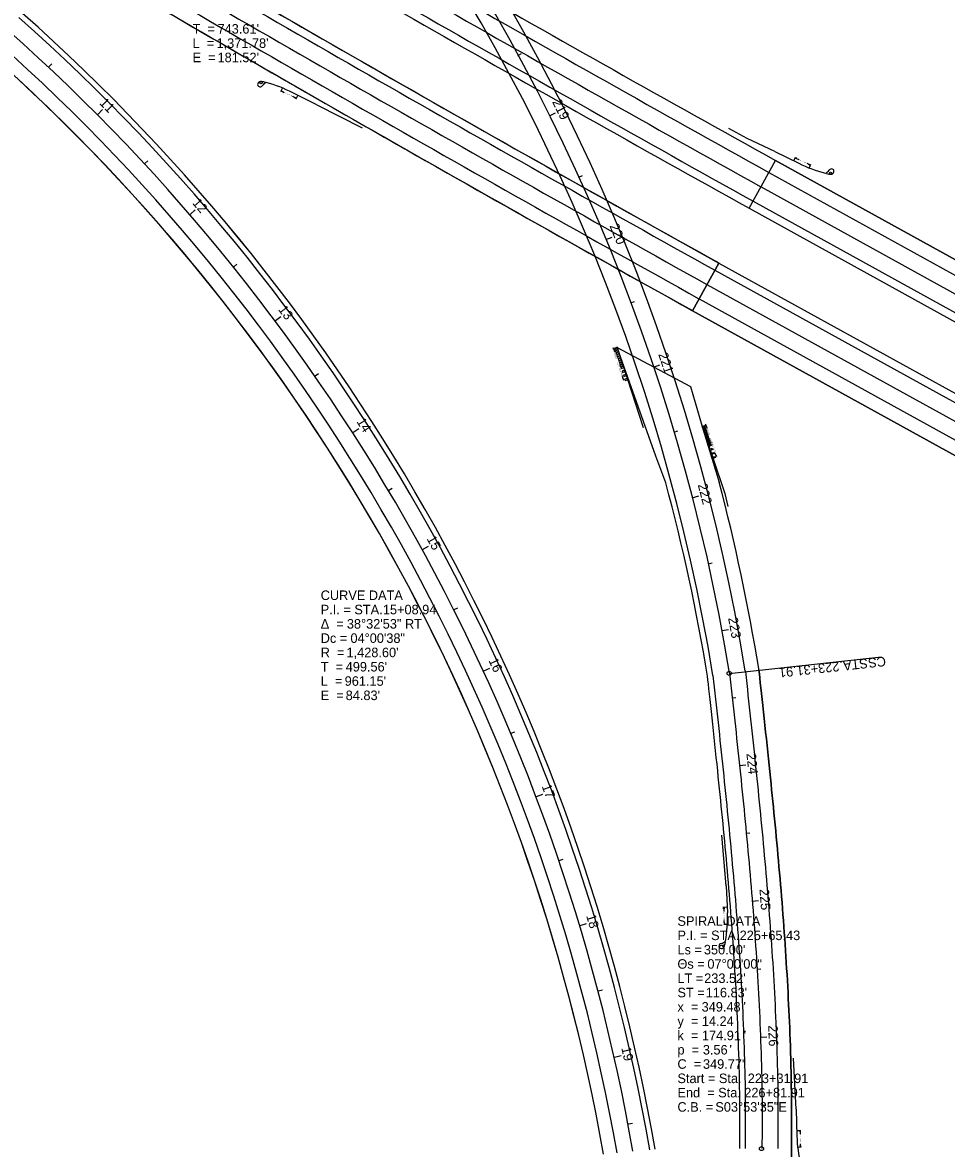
# Model space of a CAD drawing. Extents: x 76539 to 88870, y 518807 to 527554.
# Drawn here: x 87208 to 87887, y 521842 to 522669 of the extents above; entities that cross this region are included whole.
import ezdxf

# ---------------------------------------------------------------- set-up
doc = ezdxf.new("R2010")
doc.units = 0
for name, color, linetype in [('Default', 7, 'Continuous'), ('GE_P_Alignment_100_Cardinal_Points', 7, 'Continuous'), ('GE_P_Alignment_100_Curve_Data', 7, 'Continuous'), ('GE_P_Alignment_100_Stations', 7, 'Continuous'), ('PM_P_Edge_Line', 7, 'Continuous'), ('PM_P_Lane_Line', 7, 'Continuous'), ('PV_P_Shoulder', 7, 'Continuous'), ('RD_P_GR_Lt', 7, 'Continuous'), ('RD_P_GR_Rt', 7, 'Continuous'), ('SC_Scratch1', 7, 'Continuous'), ('SC_Scratch13', 7, 'Continuous'), ('XS_P_Pavt_Surface', 7, 'Continuous')]:
    doc.layers.add(name, color=color, linetype=linetype)

msp = doc.modelspace()

# ---------------------------------------------------------------- linework, layer by layer
at = {"layer": 'Default'}
for points in [[(87727.6, 522191.42), (87728.86, 522179.82), (87731.39, 522156.63), (87735.11, 522121.82), (87738.65, 522087), (87741.93, 522052.15), (87744.88, 522017.27), (87747.39, 521982.36), (87749.41, 521947.41), (87750.8, 521912.43), (87751.57, 521877.43), (87751.42, 521854.09), (87751.35, 521842.42)], [(87739.2, 522192.69), (87740.46, 522181.08), (87743, 522157.87), (87746.71, 522123.02), (87750.26, 522088.13), (87753.55, 522053.18), (87756.51, 522018.17), (87759.04, 521983.1), (87761.06, 521947.97), (87762.46, 521912.77), (87763.24, 521877.6), (87763.09, 521854.17), (87763.01, 521842.48)], [(87773.02, 521842.55), (87773.03, 521849.2), (87773.33, 521872.31), (87772.44, 521914.51), (87771.06, 521947.92), (87769.03, 521983.64), (87766.5, 522018.71), (87763.55, 522053.72), (87760.19, 522089.26), (87756.83, 522122.44), (87752.37, 522164.24), (87749.86, 522187.15), (87749.14, 522193.77)]]:
    msp.add_open_spline(points, degree=3, dxfattribs=at)
at = {"layer": 'GE_P_Alignment_100_Cardinal_Points'}
msp.add_line((87727.27, 522191.38), (87839.1, 522203.58), dxfattribs=at)
for centre in [(87727.27, 522191.38), (87751.01, 521842.42)]:
    msp.add_circle(centre, 1.5, dxfattribs=at)
at = {"layer": 'GE_P_Alignment_100_Stations'}
for p, q in [((87572.1, 522645.23), (87574.73, 522646.66)), ((87227.56, 522636.73), (87229.62, 522638.92)), ((87263.4, 522601.87), (87266.95, 522605.39)), ((87595.19, 522600.89), (87599.67, 522603.12)), ((87297.99, 522565.77), (87300.2, 522567.81)), ((87616.73, 522555.77), (87619.46, 522557.01)), ((87331.3, 522528.49), (87335.09, 522531.75)), ((87636.68, 522509.92), (87641.3, 522511.83)), ((87363.29, 522490.06), (87365.63, 522491.94)), ((87655.01, 522463.41), (87657.82, 522464.46)), ((87393.91, 522450.54), (87397.92, 522453.53)), ((87671.71, 522416.28), (87676.45, 522417.87)), ((87423.13, 522409.97), (87425.6, 522411.68)), ((87450.91, 522368.4), (87455.12, 522371.11)), ((87686.76, 522368.6), (87689.64, 522369.45)), ((87477.22, 522325.89), (87479.8, 522327.42)), ((87700.13, 522320.42), (87704.97, 522321.68)), ((87502.03, 522282.48), (87506.41, 522284.88)), ((87711.82, 522271.81), (87714.74, 522272.46)), ((87525.3, 522238.23), (87527.98, 522239.58)), ((87721.79, 522222.82), (87726.71, 522223.73)), ((87547.01, 522193.19), (87551.56, 522195.28)), ((87729.23, 522173.4), (87732.21, 522173.72)), ((87567.13, 522147.42), (87569.9, 522148.58)), ((87734.55, 522123.68), (87739.52, 522124.2)), ((87585.64, 522100.97), (87590.32, 522102.74)), ((87739.53, 522073.93), (87742.52, 522074.22)), ((87602.51, 522053.91), (87605.35, 522054.87)), ((87743.93, 522024.13), (87748.91, 522024.53)), ((87617.72, 522006.28), (87622.51, 522007.72)), ((87747.49, 521974.25), (87750.48, 521974.44)), ((87631.26, 521958.15), (87634.16, 521958.91)), ((87749.96, 521924.32), (87754.96, 521924.5)), ((87643.11, 521909.58), (87647.98, 521910.67)), ((87751.1, 521874.33), (87754.1, 521874.36)), ((87653.24, 521860.62), (87656.19, 521861.17))]:
    msp.add_line(p, q, dxfattribs=at)
at = {"layer": 'PM_P_Edge_Line'}
for p, q in [((87756.48, 522559.22), (87756.49, 522559.21)), ((87756.49, 522559.21), (88837.59, 521962.47)), ((87744.82, 522538.24), (87744.86, 522538.22)), ((87744.86, 522538.22), (88825.99, 521941.45)), ((87716.74, 522487.52), (87716.78, 522487.5)), ((87716.78, 522487.5), (88840.17, 521867.4)), ((87705.09, 522466.54), (87705.15, 522466.5)), ((87705.15, 522466.5), (88828.57, 521846.39)), ((87739.11, 522193.31), (87739.16, 522193)), ((87739.11, 522193.31), (87739.16, 522193)), ((87739.16, 522193), (87739.2, 522192.69)), ((87739.16, 522193), (87739.2, 522192.69)), ((87739.02, 521842.59), (87739.01, 521842.36))]:
    msp.add_line(p, q, dxfattribs=at)
for centre, radius, start, end in [((86313.45, 521961.45), 1444.39, 9.23728, 64.10866), ((86313.45, 521961.45), 1444.39, 9.23728, 64.10866), ((86313.45, 521961.45), 1420.39, 9.24998, 64.10866), ((98861.51, 542544.07), 22862.98, 239.568441, 240.940285), ((98861.51, 542544.07), 22886.98, 239.568441, 240.940285), ((98861.51, 542544.07), 22944.95, 239.568441, 240.940516), ((98861.51, 542544.07), 22968.95, 239.568441, 240.940516), ((86249.47, 521595.47), 1440.6, 9.83522, 48.42092), ((86249.47, 521595.47), 1416.6, 9.91089, 48.42092)]:
    msp.add_arc(centre, radius, start, end, dxfattribs=at)
for points in [[(87739.2, 522192.69), (87740.46, 522181.08), (87743, 522157.87), (87746.71, 522123.02), (87750.26, 522088.13), (87753.55, 522053.18), (87756.51, 522018.17), (87759.04, 521983.1), (87761.06, 521947.97), (87762.46, 521912.77), (87763.24, 521877.6), (87763.09, 521854.17), (87763.01, 521842.48)], [(87715.37, 522189.77), (87716.63, 522178.28), (87719.14, 522155.21), (87722.84, 522120.55), (87726.37, 522085.81), (87729.65, 522051.06), (87732.58, 522016.32), (87735.09, 521981.57), (87737.09, 521946.82), (87738.47, 521912.06), (87739.24, 521877.32), (87739.09, 521854.16), (87739.02, 521842.59)]]:
    msp.add_open_spline(points, degree=3, dxfattribs=at)
at = {"layer": 'PM_P_Lane_Line'}
for p, q in [((87750.65, 522548.73), (87750.68, 522548.72)), ((87750.68, 522548.72), (88831.79, 521951.96)), ((87710.91, 522477.03), (87710.96, 522477)), ((87710.96, 522477), (88834.37, 521856.9)), ((87727.6, 522191.44), (87727.6, 522191.43)), ((87727.6, 522191.43), (87727.6, 522191.42))]:
    msp.add_line(p, q, dxfattribs=at)
for centre, radius, start, end in [((86313.45, 521961.45), 1432.72, 9.23728, 64.10866), ((98861.51, 542544.07), 22874.98, 239.568441, 240.940285), ((98861.51, 542544.07), 22956.95, 239.568441, 240.940516), ((86249.47, 521595.47), 1428.27, 9.87385, 48.42092)]:
    msp.add_arc(centre, radius, start, end, dxfattribs=at)
at = {"layer": 'PV_P_Shoulder'}
for p, q in [((87761.34, 522567.96), (88842.42, 521971.22)), ((87741.91, 522533), (87741.96, 522532.97)), ((87741.96, 522532.97), (88820.79, 521937.47)), ((87719.66, 522492.76), (87719.68, 522492.75)), ((87719.68, 522492.75), (88843.07, 521872.66)), ((87700.23, 522457.8), (87700.3, 522457.76)), ((87700.3, 522457.76), (88823.74, 521837.64)), ((87673.43, 522350.94), (87645.03, 522430.75)), ((87707.42, 522372.8), (87719.87, 522331.9)), ((87680.69, 522331.33), (87673.43, 522350.94)), ((87749.08, 522194.34), (87748.98, 522194.92)), ((87749.14, 522193.77), (87749.08, 522194.34)), ((87735.01, 521842.35), (87735.02, 521842.61)), ((87781.67, 521223.03), (87773.02, 521842.55))]:
    msp.add_line(p, q, dxfattribs=at)
for centre, radius, start, end in [((98861.51, 542544.07), 22852.98, 239.568441, 240.940285), ((98861.51, 542544.07), 22892.98, 239.568441, 240.940285), ((98861.51, 542544.07), 22938.95, 239.568441, 240.940516), ((98861.51, 542544.07), 22978.95, 239.568441, 240.940516), ((86249.47, 521595.47), 1444.6, 9.8228, 48.42092), ((86249.47, 521595.47), 1406.6, 9.94301, 48.42092), ((86313.45, 521961.45), 1454.39, 9.23728, 14.75662), ((86313.45, 521961.45), 1416.39, 9.25428, 15.13785)]:
    msp.add_arc(centre, radius, start, end, dxfattribs=at)
msp.add_open_spline([(87735.02, 521842.61), (87735.03, 521849.22), (87735.33, 521872.02), (87734.45, 521913.53), (87733.09, 521946.44), (87731.08, 521981.62), (87728.58, 522016.2), (87725.66, 522050.76), (87722.34, 522085.87), (87719.02, 522118.68), (87714.61, 522159.99), (87712.12, 522182.65), (87711.41, 522189.23)], degree=3, dxfattribs=at)
at = {"layer": 'RD_P_GR_Lt'}
for p, q in [((87424.3, 522608.9), (87406.68, 522617.81)), ((87760.71, 522574.74), (87778.4, 522565.98)), ((87644.84, 522431.33), (87652.52, 522407.54)), ((87707.22, 522373.37), (87715.21, 522349.68)), ((87725.17, 522035.31), (87721.93, 522072.67)), ((87776.45, 521871.32), (87777.01, 521851.58))]:
    msp.add_line(p, q, dxfattribs=at)
for points in [[(87643.38, 522429.73), (87643.68, 522428.79), (87645.47, 522429.37), (87645.17, 522430.31)], [(87643.86, 522428.25), (87644.16, 522427.31), (87645.95, 522427.89), (87645.65, 522428.82)], [(87644.34, 522426.76), (87644.64, 522425.82), (87646.43, 522426.4), (87646.13, 522427.34)], [(87644.82, 522425.27), (87645.12, 522424.33), (87646.91, 522424.91), (87646.61, 522425.85)], [(87645.3, 522423.79), (87645.6, 522422.85), (87647.39, 522423.42), (87647.09, 522424.36)], [(87645.78, 522422.3), (87646.08, 522421.36), (87647.87, 522421.94), (87647.57, 522422.88)], [(87646.25, 522420.81), (87646.56, 522419.87), (87648.35, 522420.45), (87648.05, 522421.39)], [(87646.73, 522419.32), (87647.04, 522418.39), (87648.83, 522418.96), (87648.53, 522419.9)], [(87647.21, 522417.84), (87647.52, 522416.9), (87649.31, 522417.48), (87649.01, 522418.42)], [(87647.69, 522416.35), (87648, 522415.41), (87649.79, 522415.99), (87649.49, 522416.93)], [(87648.65, 522413.38), (87648.96, 522412.44), (87650.75, 522413.02), (87650.45, 522413.95)], [(87649.61, 522410.4), (87649.92, 522409.46), (87651.71, 522410.04), (87651.41, 522410.98)], [(87650.57, 522407.43), (87650.87, 522406.49), (87652.67, 522407.07), (87652.37, 522408.01)], [(87709.35, 522372.96), (87709.67, 522372.03), (87707.88, 522371.43), (87707.56, 522372.36)], [(87709.85, 522371.48), (87710.16, 522370.55), (87708.38, 522369.94), (87708.06, 522370.88)], [(87710.35, 522370), (87710.66, 522369.07), (87708.88, 522368.46), (87708.56, 522369.4)], [(87710.85, 522368.52), (87711.16, 522367.59), (87709.38, 522366.98), (87709.06, 522367.92)], [(87711.35, 522367.04), (87711.66, 522366.11), (87709.88, 522365.5), (87709.56, 522366.44)], [(87711.85, 522365.56), (87712.16, 522364.62), (87710.38, 522364.02), (87710.06, 522364.96)], [(87712.35, 522364.08), (87712.66, 522363.14), (87710.88, 522362.54), (87710.56, 522363.48)], [(87712.85, 522362.6), (87713.16, 522361.66), (87711.38, 522361.06), (87711.06, 522362)], [(87713.34, 522361.12), (87713.66, 522360.18), (87711.87, 522359.58), (87711.56, 522360.52)], [(87713.84, 522359.64), (87714.16, 522358.7), (87712.37, 522358.1), (87712.06, 522359.04)], [(87714.84, 522356.68), (87715.16, 522355.74), (87713.37, 522355.14), (87713.06, 522356.07)], [(87715.84, 522353.71), (87716.16, 522352.78), (87714.37, 522352.18), (87714.06, 522353.11)], [(87716.84, 522350.75), (87717.15, 522349.82), (87715.37, 522349.22), (87715.05, 522350.15)]]:
    msp.add_lwpolyline(points, close=True, dxfattribs=at)
msp.add_lwpolyline([(87715.21, 522349.68), (87724.02, 522323.56), (87726.35, 522313.88)], dxfattribs=at)
for centre, start, end in [((87361.32, 522528.12), 63.17242, 75.07742), ((87823.02, 522656.03), 243.63945, 255.54445), ((87877.48, 521854.44), 181.62988, 193.53487)]:
    msp.add_arc(centre, 100.51, start, end, dxfattribs=at)
at = {"layer": 'RD_P_GR_Rt'}
for p, q in [((87424.3, 522608.9), (87457.76, 522591.98)), ((87652.52, 522407.54), (87664.03, 522371.84)), ((87725.17, 522035.31), (87725.97, 522015.59)), ((87776.45, 521871.32), (87774.44, 521908.89))]:
    msp.add_line(p, q, dxfattribs=at)
msp.add_lwpolyline([(87760.71, 522574.74), (87740.49, 522584.11), (87727.11, 522591.59)], dxfattribs=at)
for centre in [(87383.33, 522625.25), (87801.81, 522558.73), (87723.06, 521991.26)]:
    msp.add_circle(centre, 0.79, dxfattribs=at)
msp.add_arc((87625.55, 522011.49), 100.51, 350.43205, 2.33705, dxfattribs=at)
for centre, major_axis, start_param, end_param in [((87382.81, 522624.08), (-1.02, -1.71), 3.668244, 7.768795), ((87382.44, 522615.84), (5.32, 8.9), 0.162527, 0.519896), ((87388.73, 522619.93), (2.92, 4.89), 0.847713, 1.513095), ((87796.36, 522564), (-2.88, -4.92), 0.847713, 1.513095), ((87802.62, 522568.14), (-5.25, -8.94), 0.162527, 0.519896), ((87802.32, 522559.9), (1.01, 1.72), 3.668244, 7.768795), ((87721.78, 521991.27), (-1.98, -0.22), 4.797576, 8.898127), ((87720.46, 521998.38), (5.66, 0.63), 4.770091, 5.435472), ((87714.13, 521994.35), (10.3, 1.15), 5.763289, 6.120658)]:
    msp.add_ellipse(centre, major_axis=major_axis, ratio=0.944544, start_param=start_param, end_param=end_param, dxfattribs=at)
at = {"layer": 'SC_Scratch1'}
for p, q in [((87398.04, 522618.78), (87399.05, 522621.28)), ((87398.22, 522619.24), (87399.25, 522618.95)), ((87399.06, 522618.58), (87398.22, 522619.24)), ((87399.25, 522618.95), (87399.06, 522618.58)), ((87399.16, 522618.77), (87400.47, 522618.1)), ((87408.27, 522614.16), (87406.73, 522614.94)), ((87408.37, 522614.34), (87408.18, 522613.97)), ((87408.18, 522613.97), (87409.21, 522613.69)), ((87409.21, 522613.69), (87408.37, 522614.34)), ((87410.35, 522615.95), (87408.95, 522613.18)), ((87774.71, 522567.81), (87776.09, 522570.59)), ((87775.84, 522570.08), (87776.68, 522569.43)), ((87776.87, 522569.8), (87775.84, 522570.08)), ((87776.68, 522569.43), (87776.87, 522569.8)), ((87776.77, 522569.62), (87778.33, 522568.85)), ((87785.93, 522565.08), (87784.6, 522565.74)), ((87785.84, 522564.89), (87786.02, 522565.27)), ((87786.86, 522564.62), (87785.84, 522564.89)), ((87786.02, 522565.27), (87786.86, 522564.62)), ((87787.05, 522565.08), (87786.06, 522562.57)), ((87725.8, 522019.7), (87722.7, 522019.57)), ((87723.1, 522018.54), (87723.27, 522019.6)), ((87723.52, 522018.56), (87723.1, 522018.54)), ((87723.27, 522019.6), (87723.52, 522018.56)), ((87723.31, 522018.55), (87723.38, 522016.82)), ((87723.72, 522008.34), (87723.66, 522009.82)), ((87723.27, 522007.32), (87725.96, 522007.21)), ((87723.93, 522008.35), (87723.52, 522008.34)), ((87723.52, 522008.34), (87723.77, 522007.3)), ((87723.77, 522007.3), (87723.93, 522008.35)), ((87776.89, 521855.7), (87780, 521855.79)), ((87779.43, 521855.77), (87779.25, 521854.72)), ((87779.25, 521854.72), (87779.67, 521854.73)), ((87779.67, 521854.73), (87779.43, 521855.77)), ((87779.46, 521854.73), (87779.51, 521852.99)), ((87780.28, 521843.52), (87777.6, 521843.22)), ((87779.55, 521844.51), (87779.96, 521844.52)), ((87779.78, 521843.47), (87779.55, 521844.51)), ((87779.75, 521844.51), (87779.71, 521845.99)), ((87779.96, 521844.52), (87779.78, 521843.47))]:
    msp.add_line(p, q, dxfattribs=at)
at = {"layer": 'SC_Scratch13'}
for p, q in [((87645.03, 522430.75), (87642.43, 522429.92)), ((87644.84, 522431.33), (87645.03, 522430.75)), ((87642.23, 522429.39), (87642.11, 522430.45)), ((87642.11, 522430.45), (87642.63, 522429.52)), ((87642.63, 522429.52), (87642.23, 522429.39)), ((87642.43, 522429.45), (87642.96, 522427.8)), ((87649.47, 522407.65), (87648.93, 522409.3)), ((87649.66, 522407.71), (87649.27, 522407.59)), ((87649.27, 522407.59), (87649.79, 522406.66)), ((87649.79, 522406.66), (87649.66, 522407.71)), ((87707.22, 522373.37), (87707.42, 522372.8)), ((87707.42, 522372.8), (87710.01, 522373.67)), ((87710.47, 522373.37), (87709.94, 522374.29)), ((87709.94, 522374.29), (87710.08, 522373.23)), ((87710.08, 522373.23), (87710.47, 522373.37)), ((87710.28, 522373.3), (87710.83, 522371.66)), ((87717.6, 522351.59), (87717.04, 522353.23)), ((87717.4, 522351.52), (87717.79, 522351.66)), ((87717.93, 522350.6), (87717.4, 522351.52)), ((87717.79, 522351.66), (87717.93, 522350.6))]:
    msp.add_line(p, q, dxfattribs=at)
at = {"layer": 'XS_P_Pavt_Surface'}
for p, q in [((87741.91, 522533), (87761.34, 522567.96)), ((88842.42, 521971.22), (87761.34, 522567.96)), ((87741.96, 522532.97), (88823.09, 521936.2)), ((87700.3, 522457.76), (87719.68, 522492.75)), ((87719.68, 522492.75), (88843.07, 521872.66)), ((88823.74, 521837.64), (87700.3, 522457.76)), ((87673.43, 522350.94), (87645.03, 522430.75)), ((87773.02, 521842.55), (87781.67, 521223.03))]:
    msp.add_line(p, q, dxfattribs=at)
for points in [[(87666.21, 522522.56), (87719.68, 522492.75), (87700.3, 522457.76), (87699.94, 522457.96)], [(87645.03, 522430.75), (87698.87, 522402.02), (87707.42, 522372.8)]]:
    msp.add_lwpolyline(points, dxfattribs=at)
for centre, radius, start, end in [((98861.51, 542544.07), 22852.98, 239.568441, 240.940285), ((98861.51, 542544.07), 22892.98, 239.568441, 240.940285), ((99004.35, 542793.24), 23226.15, 239.567729, 240.780111), ((99002.02, 542789.93), 23262.12, 239.568441, 240.931339), ((86249.46, 521595.47), 1444.6, 9.8228, 48.42092), ((86249.77, 521595.64), 1406.27, 9.93828, 48.41618), ((86313.45, 521961.45), 1454.39, 9.23728, 14.75662), ((86313.45, 521961.45), 1416.39, 9.25428, 15.13785)]:
    msp.add_arc(centre, radius, start, end, dxfattribs=at)
for points in [[(87749.14, 522193.77), (87749.86, 522187.15), (87752.37, 522164.24), (87756.83, 522122.44), (87760.19, 522089.26), (87763.55, 522053.72), (87766.5, 522018.71), (87769.03, 521983.64), (87771.06, 521947.92), (87772.44, 521914.51), (87773.33, 521872.31), (87773.03, 521849.2), (87773.02, 521842.55)], [(87735.02, 521842.61), (87735.03, 521849.22), (87735.33, 521872.02), (87734.45, 521913.53), (87733.09, 521946.44), (87731.08, 521981.62), (87728.57, 522016.2), (87725.66, 522050.76), (87722.34, 522085.87), (87719.02, 522118.68), (87714.61, 522159.99), (87712.12, 522182.65), (87711.41, 522189.23)]]:
    msp.add_open_spline(points, degree=3, dxfattribs=at)

# ---------------------------------------------------------------- texts
at = {"layer": 'GE_P_Alignment_100_Cardinal_Points'}
for s, p in [('223+31.91', (87807.8, 522200.06)), (' STA. ', (87831.29, 522202.63)), ('CS', (87841.98, 522203.79))]:
    msp.add_text(s, height=7, rotation=186.22609, dxfattribs=at).set_placement(p)
at = {"layer": 'GE_P_Alignment_100_Curve_Data'}
for s, p in [('T  = ', (87333.1, 522661.22)), ("743.61'", (87351.44, 522661.22)), ('L  = ', (87333.1, 522650.72)), ("1,371.78'", (87350.7, 522650.72)), ('E  = ', (87333.1, 522640.22)), ("181.52'", (87351.45, 522640.22)), ('CURVE DATA', (87427.23, 522245.27)), ('P.I. = STA. ', (87427.23, 522234.77)), ('15+08.94', (87472.9, 522234.77)), ('Δ  = ', (87427.23, 522224.27)), ('38°32\'53" RT', (87446.43, 522224.27)), ('Dc = ', (87427.23, 522213.77)), ('04°00\'38"', (87449.08, 522213.77)), ('R  = ', (87427.23, 522203.27)), ("1,428.60'", (87446.19, 522203.27)), ('T  = ', (87427.23, 522192.77)), ("499.56'", (87445.58, 522192.77)), ('L  = ', (87427.23, 522182.27)), ("961.15'", (87444.84, 522182.27)), ('E  = ', (87427.23, 522171.77)), ("84.83'", (87445.59, 522171.77)), ('SPIRAL DATA', (87689.29, 522006)), ('P.I. = STA. ', (87689.29, 521995.5)), ('225+65.43', (87734.96, 521995.5)), ('Ls = ', (87689.29, 521985)), ("350.00'", (87708.7, 521985)), ('Θs = ', (87689.29, 521974.5)), ('07°00\'00"', (87711.3, 521974.5)), ('LT = ', (87689.29, 521964)), ("233.52'", (87708.93, 521964)), ('ST = ', (87689.29, 521953.5)), ("116.83'", (87710.06, 521953.5)), ('x  = ', (87689.29, 521943)), ('349.48', (87707.04, 521943)), ("'", (87737.76, 521943)), ('y  = ', (87689.29, 521932.5)), ('14.24', (87707.2, 521932.5)), ("'", (87732.33, 521932.5)), ('k  = ', (87689.29, 521922)), ('174.91', (87707.28, 521922)), ("'", (87738, 521922)), ('3.56', (87707.93, 521911.5)), ("'", (87727.48, 521911.5)), ('p  = ', (87689.29, 521911.5)), ('C  = ', (87689.29, 521901)), ("349.77'", (87708.03, 521901)), ('Start = Sta. ', (87689.29, 521890.5)), ('223+31.91', (87740.93, 521890.5)), ('End  = Sta. ', (87689.29, 521880)), ('226+81.91', (87738.38, 521880)), ('C.B. = ', (87689.29, 521869.5)), ('S03°53\'35"E', (87717.11, 521869.5))]:
    msp.add_text(s, height=7, dxfattribs=at).set_placement(p)
at = {"layer": 'GE_P_Alignment_100_Stations'}
for s, rotation, p in [('11', 314.78633, (87264.25, 522609.88)), ('219', 296.51374, (87597.08, 522611.1)), ('12', 310.77571, (87332.51, 522536.66)), ('220', 292.51373, (87639.25, 522520.04)), ('13', 306.76508, (87395.69, 522458.59)), ('221', 288.51371, (87675.14, 522425.73)), ('14', 302.75446, (87453.26, 522376.31)), ('222', 284.5137, (87704.13, 522329.93)), ('15', 298.74383, (87504.88, 522290.28)), ('223', 280.51369, (87726.45, 522232)), ('16', 294.73321, (87550.35, 522200.89)), ('224', 275.96116, (87739.91, 522132.47)), ('17', 290.72258, (87589.45, 522108.56)), ('225', 274.61155, (87749.49, 522032.86)), ('18', 286.71196, (87622.12, 522013.39)), ('226', 272.11909, (87755.9, 521932.94)), ('19', 282.70134, (87647.99, 521916.32))]:
    msp.add_text(s, height=7, rotation=rotation, dxfattribs=at).set_placement(p)
at = {"layer": 'SC_Scratch1'}
for rotation, p in [(333.16948, (87400.51, 522617.74)), (153.63651, (87784.56, 522566.1)), (92.33999, (87723.9, 522010.03)), (91.62694, (87780.01, 521846.19))]:
    msp.add_text('LENGTH OF NEED', height=0.5506, rotation=rotation, dxfattribs=at).set_placement(p)
at = {"layer": 'SC_Scratch13'}
for s, height, rotation, p in [('BRIDGE', 1.045, 107.87825, (87645.09, 522422.86)), ("MGS(MIN. 12.5')", 1.0451, 107.87825, (87649.38, 522409.56)), ('BRIDGE', 1.045, 288.63663, (87710.37, 522371.42)), ("MGS(MIN. 12.5')", 1.0451, 288.63663, (87712.93, 522363.83))]:
    msp.add_text(s, height=height, rotation=rotation, dxfattribs=at).set_placement(p)

doc.saveas('drawing.dxf')
